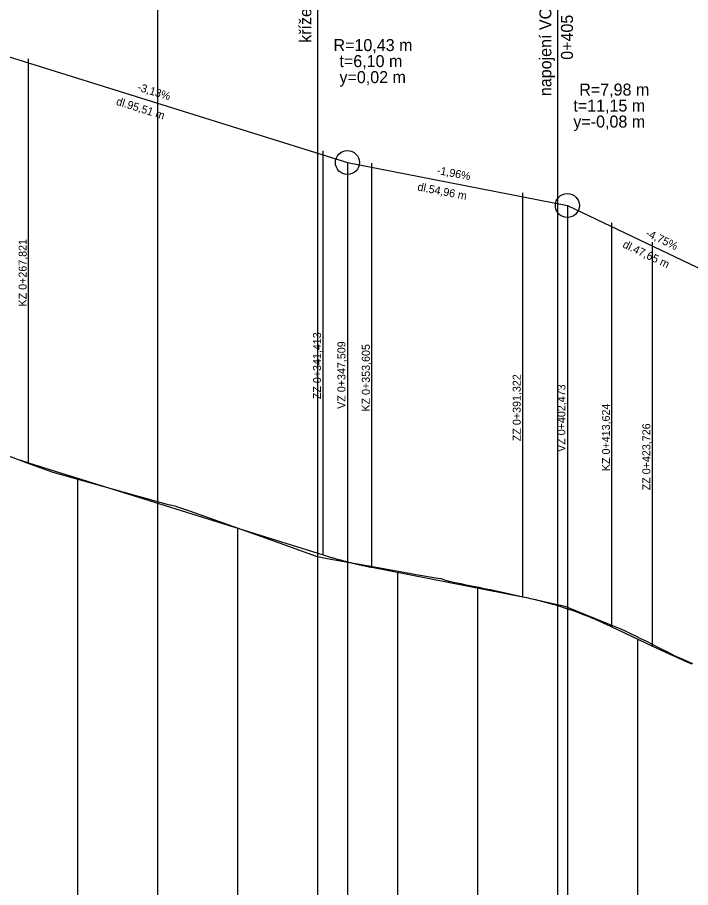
# Model space of a CAD drawing. Extents: x -632716 to -629545, y -1094726 to -1088285.
# Drawn here: x -632178.9 to -632010.6, y -1089374.5 to -1089157 of the extents above; entities that cross this region are included whole.
import ezdxf

# ---------------------------------------------------------------- set-up
doc = ezdxf.new("R2010")
doc.units = 0
for name, color, linetype in [('20', 7, 'Continuous'), ('Default', 7, 'Continuous'), ('SKLONY_NIVELETA', 7, 'Continuous'), ('SKLONY_POPIS', 7, 'Continuous'), ('TECNY_NIVELETA', 7, 'Continuous'), ('VOZOVKA', 7, 'Continuous')]:
    doc.layers.add(name, color=color, linetype=linetype)

msp = doc.modelspace()

# ---------------------------------------------------------------- linework, layer by layer
at = {"layer": '20'}
for points in [[(-632163.88, -1089272.15), (-632163.88, -1089386.44), (-632163.88, -1089436.44), (-632163.88, -1089376.44)], [(-632143.88, -1089278.41), (-632143.88, -1089386.44), (-632143.88, -1089436.44), (-632143.88, -1089376.44)], [(-632123.88, -1089284.66), (-632123.88, -1089386.44), (-632123.88, -1089436.44), (-632123.88, -1089376.44)], [(-632103.88, -1089290.92), (-632103.88, -1089386.44), (-632103.88, -1089436.44), (-632103.88, -1089376.44)], [(-632083.88, -1089295.71), (-632083.88, -1089386.44), (-632083.88, -1089436.44), (-632083.88, -1089376.44)], [(-632063.88, -1089299.63), (-632063.88, -1089386.44), (-632063.88, -1089436.44), (-632063.88, -1089376.44)], [(-632043.88, -1089304.02), (-632043.88, -1089386.44), (-632043.88, -1089436.44), (-632043.88, -1089376.44)], [(-632023.88, -1089312.37), (-632023.88, -1089386.44), (-632023.88, -1089436.44), (-632023.88, -1089376.44)]]:
    msp.add_lwpolyline(points, dxfattribs=at)
at = {"layer": 'Default'}
for p, q in [((-632176.06, -1089268.34), (-632102.47, -1089291.36)), ((-632176.06, -1089268.34), (-632102.47, -1089291.36)), ((-632090.28, -1089294.46), (-632052.56, -1089301.85)), ((-632090.28, -1089294.46), (-632052.56, -1089301.85)), ((-632030.26, -1089309.33), (-632020.16, -1089314.14)), ((-632030.26, -1089309.33), (-632020.16, -1089314.14))]:
    msp.add_line(p, q, dxfattribs=at)
for points in [[(-632179.36, -1089267.28), (-632178.7, -1089267.5), (-632178.04, -1089267.71), (-632177.38, -1089267.92), (-632176.72, -1089268.13), (-632176.06, -1089268.34)], [(-632179.36, -1089267.28), (-632178.7, -1089267.5), (-632178.04, -1089267.71), (-632177.38, -1089267.92), (-632176.72, -1089268.13), (-632176.06, -1089268.34)], [(-632102.47, -1089291.36), (-632102.22, -1089291.44), (-632101.96, -1089291.52), (-632101.71, -1089291.59), (-632101.46, -1089291.67), (-632101.2, -1089291.75), (-632100.95, -1089291.82), (-632100.69, -1089291.9), (-632100.44, -1089291.97), (-632100.19, -1089292.05), (-632099.93, -1089292.12), (-632099.68, -1089292.2), (-632099.42, -1089292.27), (-632099.17, -1089292.34), (-632098.92, -1089292.41), (-632098.66, -1089292.48), (-632098.41, -1089292.55), (-632098.15, -1089292.62), (-632097.9, -1089292.69), (-632097.65, -1089292.76), (-632097.39, -1089292.82), (-632097.14, -1089292.89), (-632096.88, -1089292.96), (-632096.63, -1089293.02), (-632096.12, -1089293.15), (-632095.87, -1089293.22), (-632095.61, -1089293.28), (-632095.36, -1089293.34), (-632095.11, -1089293.4), (-632094.85, -1089293.46), (-632094.6, -1089293.52), (-632094.34, -1089293.58), (-632094.09, -1089293.64), (-632093.84, -1089293.7), (-632093.58, -1089293.76), (-632093.33, -1089293.82), (-632093.07, -1089293.87), (-632092.82, -1089293.93), (-632092.57, -1089293.99), (-632092.31, -1089294.04), (-632092.06, -1089294.1), (-632091.8, -1089294.15), (-632091.55, -1089294.2), (-632091.3, -1089294.26), (-632091.04, -1089294.31), (-632090.79, -1089294.36), (-632090.53, -1089294.41), (-632090.28, -1089294.46)], [(-632102.47, -1089291.36), (-632102.22, -1089291.44), (-632101.96, -1089291.52), (-632101.71, -1089291.59), (-632101.46, -1089291.67), (-632101.2, -1089291.75), (-632100.95, -1089291.82), (-632100.69, -1089291.9), (-632100.44, -1089291.97), (-632100.19, -1089292.05), (-632099.93, -1089292.12), (-632099.68, -1089292.2), (-632099.42, -1089292.27), (-632099.17, -1089292.34), (-632098.92, -1089292.41), (-632098.66, -1089292.48), (-632098.41, -1089292.55), (-632098.15, -1089292.62), (-632097.9, -1089292.69), (-632097.65, -1089292.76), (-632097.39, -1089292.82), (-632097.14, -1089292.89), (-632096.88, -1089292.96), (-632096.63, -1089293.02), (-632096.12, -1089293.15), (-632095.87, -1089293.22), (-632095.61, -1089293.28), (-632095.36, -1089293.34), (-632095.11, -1089293.4), (-632094.85, -1089293.46), (-632094.6, -1089293.52), (-632094.34, -1089293.58), (-632094.09, -1089293.64), (-632093.84, -1089293.7), (-632093.58, -1089293.76), (-632093.33, -1089293.82), (-632093.07, -1089293.87), (-632092.82, -1089293.93), (-632092.57, -1089293.99), (-632092.31, -1089294.04), (-632092.06, -1089294.1), (-632091.8, -1089294.15), (-632091.55, -1089294.2), (-632091.3, -1089294.26), (-632091.04, -1089294.31), (-632090.79, -1089294.36), (-632090.53, -1089294.41), (-632090.28, -1089294.46)], [(-632052.56, -1089301.85), (-632052.1, -1089301.94), (-632051.63, -1089302.04), (-632051.17, -1089302.13), (-632050.7, -1089302.24), (-632050.24, -1089302.34), (-632049.78, -1089302.44), (-632049.31, -1089302.55), (-632048.85, -1089302.66), (-632048.38, -1089302.78), (-632047.92, -1089302.89), (-632047.45, -1089303.01), (-632046.99, -1089303.14), (-632046.52, -1089303.26), (-632046.06, -1089303.39), (-632045.59, -1089303.52), (-632045.13, -1089303.65), (-632044.66, -1089303.79), (-632044.2, -1089303.93), (-632043.73, -1089304.07), (-632043.27, -1089304.21), (-632042.81, -1089304.36), (-632042.34, -1089304.51), (-632041.88, -1089304.66), (-632040.95, -1089304.97), (-632040.48, -1089305.13), (-632040.02, -1089305.29), (-632039.55, -1089305.46), (-632039.09, -1089305.63), (-632038.62, -1089305.8), (-632038.16, -1089305.97), (-632037.69, -1089306.15), (-632037.23, -1089306.33), (-632036.77, -1089306.51), (-632036.3, -1089306.69), (-632035.84, -1089306.88), (-632035.37, -1089307.07), (-632034.91, -1089307.26), (-632034.44, -1089307.46), (-632033.98, -1089307.65), (-632033.51, -1089307.85), (-632033.05, -1089308.06), (-632032.58, -1089308.26), (-632032.12, -1089308.47), (-632031.65, -1089308.68), (-632031.19, -1089308.9), (-632030.73, -1089309.12), (-632030.26, -1089309.33)], [(-632052.56, -1089301.85), (-632052.1, -1089301.94), (-632051.63, -1089302.04), (-632051.17, -1089302.13), (-632050.7, -1089302.24), (-632050.24, -1089302.34), (-632049.78, -1089302.44), (-632049.31, -1089302.55), (-632048.85, -1089302.66), (-632048.38, -1089302.78), (-632047.92, -1089302.89), (-632047.45, -1089303.01), (-632046.99, -1089303.14), (-632046.52, -1089303.26), (-632046.06, -1089303.39), (-632045.59, -1089303.52), (-632045.13, -1089303.65), (-632044.66, -1089303.79), (-632044.2, -1089303.93), (-632043.73, -1089304.07), (-632043.27, -1089304.21), (-632042.81, -1089304.36), (-632042.34, -1089304.51), (-632041.88, -1089304.66), (-632040.95, -1089304.97), (-632040.48, -1089305.13), (-632040.02, -1089305.29), (-632039.55, -1089305.46), (-632039.09, -1089305.63), (-632038.62, -1089305.8), (-632038.16, -1089305.97), (-632037.69, -1089306.15), (-632037.23, -1089306.33), (-632036.77, -1089306.51), (-632036.3, -1089306.69), (-632035.84, -1089306.88), (-632035.37, -1089307.07), (-632034.91, -1089307.26), (-632034.44, -1089307.46), (-632033.98, -1089307.65), (-632033.51, -1089307.85), (-632033.05, -1089308.06), (-632032.58, -1089308.26), (-632032.12, -1089308.47), (-632031.65, -1089308.68), (-632031.19, -1089308.9), (-632030.73, -1089309.12), (-632030.26, -1089309.33)], [(-632020.16, -1089314.14), (-632019.06, -1089314.66), (-632017.96, -1089315.17), (-632016.86, -1089315.68), (-632015.76, -1089316.18), (-632014.66, -1089316.68), (-632013.56, -1089317.17), (-632012.46, -1089317.66), (-632011.36, -1089318.14), (-632010.26, -1089318.62)], [(-632020.16, -1089314.14), (-632019.06, -1089314.66), (-632017.96, -1089315.17), (-632016.86, -1089315.68), (-632015.76, -1089316.18), (-632014.66, -1089316.68), (-632013.56, -1089317.17), (-632012.46, -1089317.66), (-632011.36, -1089318.14), (-632010.26, -1089318.62)]]:
    msp.add_lwpolyline(points, dxfattribs=at)
at = {"layer": 'SKLONY_NIVELETA'}
for p, q in [((-632143.88, -1089119.01), (-632143.88, -1089278.41)), ((-632103.88, -1089131.52), (-632103.88, -1089290.92)), ((-632043.88, -1089144.63), (-632043.88, -1089304.02)), ((-632191.88, -1089163.39), (-632096.38, -1089193.27)), ((-632096.38, -1089193.27), (-632096.38, -1089436.44)), ((-632096.38, -1089193.27), (-632041.41, -1089204.03)), ((-632041.41, -1089204.03), (-632041.41, -1089436.44)), ((-632041.41, -1089204.03), (-631993.77, -1089226.68)), ((-632176.06, -1089268.34), (-632102.47, -1089291.36)), ((-632090.28, -1089294.46), (-632052.56, -1089301.85)), ((-632030.26, -1089309.33), (-632020.16, -1089314.14))]:
    msp.add_line(p, q, dxfattribs=at)
for points in [[(-632179.36, -1089267.28), (-632178.7, -1089267.5), (-632178.04, -1089267.71), (-632177.38, -1089267.92), (-632176.72, -1089268.13), (-632176.06, -1089268.34)], [(-632102.47, -1089291.36), (-632102.22, -1089291.44), (-632101.96, -1089291.52), (-632101.71, -1089291.59), (-632101.46, -1089291.67), (-632101.2, -1089291.75), (-632100.95, -1089291.82), (-632100.69, -1089291.9), (-632100.44, -1089291.97), (-632100.19, -1089292.05), (-632099.93, -1089292.12), (-632099.68, -1089292.2), (-632099.42, -1089292.27), (-632099.17, -1089292.34), (-632098.92, -1089292.41), (-632098.66, -1089292.48), (-632098.41, -1089292.55), (-632098.15, -1089292.62), (-632097.9, -1089292.69), (-632097.65, -1089292.76), (-632097.39, -1089292.82), (-632097.14, -1089292.89), (-632096.88, -1089292.96), (-632096.63, -1089293.02), (-632096.12, -1089293.15), (-632095.87, -1089293.22), (-632095.61, -1089293.28), (-632095.36, -1089293.34), (-632095.11, -1089293.4), (-632094.85, -1089293.46), (-632094.6, -1089293.52), (-632094.34, -1089293.58), (-632094.09, -1089293.64), (-632093.84, -1089293.7), (-632093.58, -1089293.76), (-632093.33, -1089293.82), (-632093.07, -1089293.87), (-632092.82, -1089293.93), (-632092.57, -1089293.99), (-632092.31, -1089294.04), (-632092.06, -1089294.1), (-632091.8, -1089294.15), (-632091.55, -1089294.2), (-632091.3, -1089294.26), (-632091.04, -1089294.31), (-632090.79, -1089294.36), (-632090.53, -1089294.41), (-632090.28, -1089294.46)], [(-632052.56, -1089301.85), (-632052.1, -1089301.94), (-632051.63, -1089302.04), (-632051.17, -1089302.13), (-632050.7, -1089302.24), (-632050.24, -1089302.34), (-632049.78, -1089302.44), (-632049.31, -1089302.55), (-632048.85, -1089302.66), (-632048.38, -1089302.78), (-632047.92, -1089302.89), (-632047.45, -1089303.01), (-632046.99, -1089303.14), (-632046.52, -1089303.26), (-632046.06, -1089303.39), (-632045.59, -1089303.52), (-632045.13, -1089303.65), (-632044.66, -1089303.79), (-632044.2, -1089303.93), (-632043.73, -1089304.07), (-632043.27, -1089304.21), (-632042.81, -1089304.36), (-632042.34, -1089304.51), (-632041.88, -1089304.66), (-632040.95, -1089304.97), (-632040.48, -1089305.13), (-632040.02, -1089305.29), (-632039.55, -1089305.46), (-632039.09, -1089305.63), (-632038.62, -1089305.8), (-632038.16, -1089305.97), (-632037.69, -1089306.15), (-632037.23, -1089306.33), (-632036.77, -1089306.51), (-632036.3, -1089306.69), (-632035.84, -1089306.88), (-632035.37, -1089307.07), (-632034.91, -1089307.26), (-632034.44, -1089307.46), (-632033.98, -1089307.65), (-632033.51, -1089307.85), (-632033.05, -1089308.06), (-632032.58, -1089308.26), (-632032.12, -1089308.47), (-632031.65, -1089308.68), (-632031.19, -1089308.9), (-632030.73, -1089309.12), (-632030.26, -1089309.33)], [(-632020.16, -1089314.14), (-632019.06, -1089314.66), (-632017.96, -1089315.17), (-632016.86, -1089315.68), (-632015.76, -1089316.18), (-632014.66, -1089316.68), (-632013.56, -1089317.17), (-632012.46, -1089317.66), (-632011.36, -1089318.14), (-632010.26, -1089318.62)]]:
    msp.add_lwpolyline(points, dxfattribs=at)
for centre in [(-632096.38, -1089193.27), (-632041.41, -1089204.03)]:
    msp.add_circle(centre, 3, dxfattribs=at)
at = {"layer": 'TECNY_NIVELETA'}
for p, q in [((-632176.06, -1089268.34), (-632176.06, -1089167.34)), ((-632102.47, -1089291.36), (-632102.47, -1089190.36)), ((-632096.38, -1089193.27), (-632096.38, -1089193.27)), ((-632090.28, -1089294.46), (-632090.28, -1089193.46)), ((-632052.56, -1089301.85), (-632052.56, -1089200.85)), ((-632041.41, -1089204.03), (-632041.41, -1089204.03)), ((-632030.26, -1089309.33), (-632030.26, -1089208.33)), ((-632020.16, -1089314.14), (-632020.16, -1089213.14))]:
    msp.add_line(p, q, dxfattribs=at)
at = {"layer": 'VOZOVKA'}
msp.add_lwpolyline([(-632193.53, -1089261.95), (-632175.56, -1089268.72), (-632169.98, -1089270.67), (-632149.85, -1089276.34), (-632141.79, -1089278.63), (-632141.49, -1089278.71), (-632140.3, -1089278.93), (-632139.5, -1089279.08), (-632138.81, -1089279.33), (-632137.32, -1089279.85), (-632135.83, -1089280.38), (-632115.5, -1089287.58), (-632104.17, -1089291.66), (-632102.31, -1089292.08), (-632101.47, -1089292.24), (-632088.67, -1089294.55), (-632087.76, -1089294.71), (-632086.85, -1089294.88), (-632085.94, -1089295.04), (-632085.03, -1089295.21), (-632084.12, -1089295.37), (-632083.21, -1089295.53), (-632082.3, -1089295.7), (-632081.49, -1089295.84), (-632081.39, -1089295.86), (-632080.48, -1089296.01), (-632079.58, -1089296.16), (-632079.24, -1089296.22), (-632078.67, -1089296.32), (-632077.69, -1089296.48), (-632076.71, -1089296.64), (-632075.74, -1089296.81), (-632074.76, -1089296.97), (-632073.78, -1089297.14), (-632073.05, -1089297.26), (-632072.81, -1089297.34), (-632071.83, -1089297.65), (-632071.04, -1089297.9), (-632070.85, -1089297.94), (-632069.88, -1089298.15), (-632068.97, -1089298.34), (-632068.06, -1089298.53), (-632067.15, -1089298.72), (-632066.24, -1089298.91), (-632065.33, -1089299.09), (-632064.42, -1089299.28), (-632063.51, -1089299.46), (-632062.6, -1089299.64), (-632061.69, -1089299.82), (-632060.78, -1089300), (-632060.6, -1089300.04), (-632059.88, -1089300.2), (-632042.03, -1089304.18), (-632031.76, -1089308.33), (-632030.09, -1089309), (-632028.43, -1089309.68), (-632028.08, -1089309.81), (-632026.76, -1089310.45), (-632025.48, -1089311.07), (-632024.2, -1089311.7), (-632022.93, -1089312.33), (-632021.65, -1089312.96), (-632020.37, -1089313.6), (-632019.09, -1089314.25), (-632017.81, -1089314.9), (-632016.53, -1089315.55), (-632015.26, -1089316.21), (-632014.7, -1089316.5), (-632013.98, -1089316.81), (-632012.7, -1089317.36), (-632011.42, -1089317.92), (-632010.14, -1089318.48)], dxfattribs=at)

# ---------------------------------------------------------------- texts
at = {"layer": 'SKLONY_POPIS'}
for s, height, rotation, p in [('křížení s HC7', 3, 90, (-632105.4, -1089163.35)), ('napojení VC15', 3, 90, (-632045.4, -1089176.67)), ('0+405', 3, 90, (-632040, -1089167.59)), ('-3,13%', 2, 342.6309, (-632149.05, -1089175.22)), ('dl.95,51 m', 2, 342.6309, (-632154.33, -1089178.8)), ('-1,96%', 2, 348.9148, (-632074.13, -1089196.1)), ('dl.54,96 m', 2, 348.9148, (-632078.99, -1089200.24)), ('-4,75%', 2, 334.5771, (-632022.03, -1089211.59)), ('KZ 0+267,821', 2, 90, (-632176.56, -1089229.26)), ('dl.47,65 m', 2, 334.5771, (-632027.76, -1089214.4)), ('ZZ 0+341,413', 2, 90, (-632102.97, -1089252.44)), ('VZ 0+347,509', 2, 90, (-632096.88, -1089254.85)), ('KZ 0+353,605', 2, 90, (-632090.78, -1089255.54)), ('ZZ 0+391,322', 2, 90, (-632053.06, -1089262.93)), ('VZ 0+402,473', 2, 90, (-632041.91, -1089265.62)), ('KZ 0+413,624', 2, 90, (-632030.76, -1089270.42)), ('ZZ 0+423,726', 2, 90, (-632020.66, -1089275.22))]:
    msp.add_text(s, height=height, rotation=rotation, dxfattribs=at).set_placement(p)
for s, p in [('R=10,43 m', (-632099.86, -1089165.41)), ('t=6,10 m', (-632098.37, -1089169.41)), ('y=0,02 m', (-632098.37, -1089173.41)), ('R=7,98 m', (-632038.43, -1089176.53)), ('t=11,15 m', (-632039.91, -1089180.53)), ('y=-0,08 m', (-632039.91, -1089184.53))]:
    msp.add_text(s, height=3, dxfattribs=at).set_placement(p)

doc.saveas('drawing.dxf')
